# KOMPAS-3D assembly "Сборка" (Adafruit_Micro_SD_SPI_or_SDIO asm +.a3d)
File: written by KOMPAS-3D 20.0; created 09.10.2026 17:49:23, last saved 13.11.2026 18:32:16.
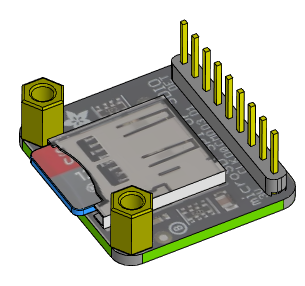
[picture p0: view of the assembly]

Document properties: Полное имя файла: D:\myProjects\Progect_esp32\box_compas\SD card\Adafruit_Micro_SD_SPI_or_SDIO asm +.a3d

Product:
- Part/product: Сборка
    Масса: 0.0110383
  - Component [detail]: Деталь  | Масса: 0.00115709; source file: ..\разъемы\pls_9.m3d
  - Component [detail]: Деталь  | Масса: 0.0074136; source file: Adafruit_Micro_SD_SPI_or_SDIO.m3d
  - Component [detail]: Деталь  | Масса: 0.00121292; source file: micro sd.m3d
  - Component [detail]: Деталь  | qty 2  | Масса: 0.000627349; source file: ..\прочее\PCHSS-6.m3d

Referenced files in D:\myProjects\Progect_esp32\box_compas\SD card\: Adafruit_Micro_SD_SPI_or_SDIO.m3d, micro sd.m3d
Referenced files in D:\myProjects\Progect_esp32\box_compas\разъемы\: pls_9.m3d
Referenced files in D:\myProjects\Progect_esp32\box_compas\прочее\: PCHSS-6.m3d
